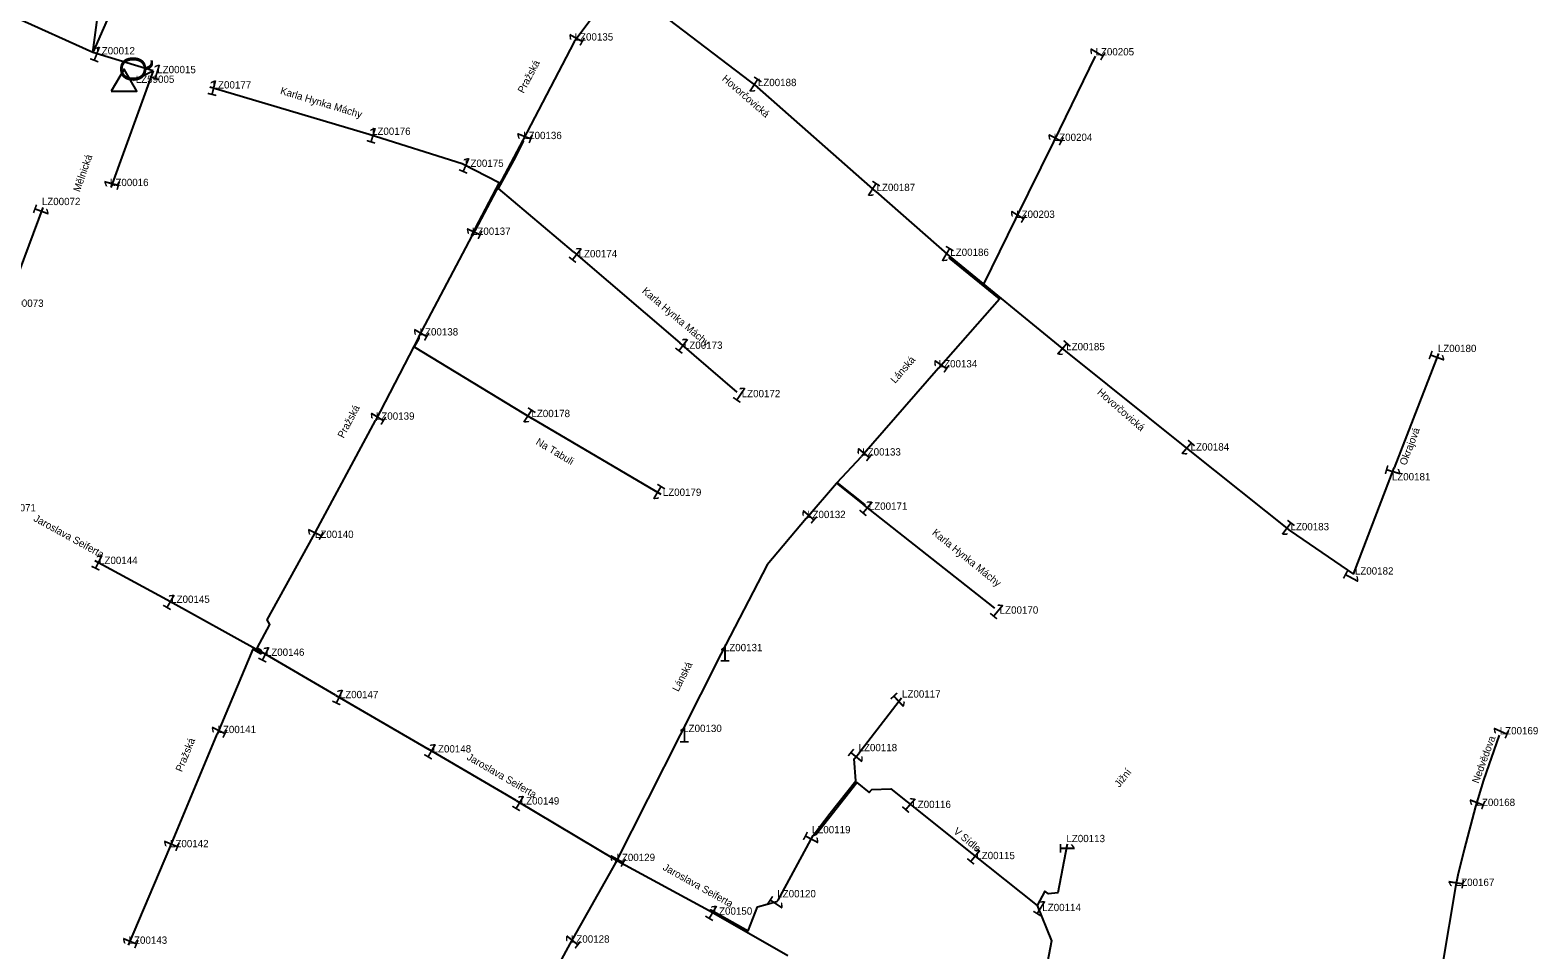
# Model space of a CAD drawing. Extents: x -736540 to -735418, y -1033000 to -1031598.
# Drawn here: x -736132 to -735616, y -1032655 to -1032341 of the extents above; entities that cross this region are included whole.
import ezdxf

# ---------------------------------------------------------------- set-up
doc = ezdxf.new("R2010")
doc.units = 0
for name, color, linetype in [('ftf_2010', 7, 'Continuous'), ('ftf_2050', 7, 'Continuous'), ('ftf_2080', 7, 'Continuous'), ('ftf_2210', 7, 'Continuous'), ('ftf_2240', 7, 'Continuous'), ('ftf_3010', 7, 'Continuous'), ('ftf_3010_ftf_3010_gtda_3015_gtda_3015_1', 7, 'Continuous'), ('ftf_3260', 7, 'Continuous'), ('ftf_3260_ftf_3260_gtda_3265_gtda_3265_1', 7, 'Continuous'), ('ftf_nu', 7, 'Continuous')]:
    doc.layers.add(name, color=color, linetype=linetype)

msp = doc.modelspace()

# ---------------------------------------------------------------- linework, layer by layer
at = {"layer": 'ftf_2010'}
for points in [[(-735916.06, -1032335.18), (-735883.11, -1032360.3)], [(-735945.72, -1032344.76), (-735963.27, -1032378.39)], [(-735767.69, -1032349.68), (-735781.89, -1032378.92)], [(-736070.38, -1032360.15), (-736015.89, -1032376.33)], [(-735842.62, -1032395.9), (-735883.11, -1032360.3)], [(-736015.89, -1032376.33), (-735984.08, -1032386.39)], [(-735963.27, -1032378.39), (-735980.62, -1032411)], [(-735946, -1032416.55), (-735971.61, -1032394.84), (-735966.42, -1032385.26), (-735963.14, -1032378.83), (-735963.27, -1032378.39)], [(-735781.89, -1032378.92), (-735794.83, -1032405.22)], [(-735984.08, -1032386.39), (-735971.41, -1032392.84), (-735980.89, -1032410.88), (-735980.62, -1032411)], [(-735842.62, -1032395.9), (-735817.38, -1032418.12)], [(-736127.45, -1032401.33), (-736140.32, -1032436.02)], [(-735794.83, -1032405.22), (-735805.8, -1032427.57)], [(-735998.88, -1032445.56), (-735980.62, -1032411)], [(-735946, -1032416.55), (-735909.66, -1032447.62)], [(-735821.15, -1032456.3), (-735800.35, -1032432.64), (-735817.39, -1032418.65), (-735817.38, -1032418.12)], [(-735817.38, -1032418.12), (-735777.75, -1032450.49)], [(-735998.88, -1032445.56), (-736013.7, -1032474.21)], [(-735998.88, -1032445.56), (-735998.88, -1032446.09), (-736000.43, -1032449.03), (-735960.4, -1032473.34)], [(-735890, -1032464.44), (-735909.66, -1032447.62)], [(-735777.75, -1032450.49), (-735735.23, -1032484.5)], [(-735650.28, -1032451.26), (-735665.39, -1032490.3)], [(-735821.15, -1032456.3), (-735847.57, -1032486.43)], [(-736034.95, -1032513.81), (-736013.7, -1032474.21)], [(-735916.05, -1032499.44), (-735960.4, -1032473.34)], [(-735846.61, -1032503.08), (-735846.43, -1032502.86), (-735855.81, -1032495.33), (-735847.57, -1032486.43)], [(-735735.23, -1032484.5), (-735700.99, -1032511.85)], [(-735679.34, -1032526.68), (-735665.39, -1032490.3)], [(-735866.45, -1032507.68), (-735856.02, -1032495.56), (-735846.61, -1032503.08)], [(-735801.94, -1032538.34), (-735846.61, -1032503.08)], [(-735866.45, -1032507.68), (-735879.73, -1032523.46), (-735895.6, -1032554)], [(-736052.56, -1032553.35), (-736052.75, -1032552.71), (-736054.14, -1032551.97), (-736049.81, -1032543.83), (-736050.76, -1032542.31), (-736034.95, -1032513.81)], [(-735700.99, -1032511.85), (-735679.34, -1032526.68)], [(-736109.63, -1032521.95), (-736085.03, -1032535.34)], [(-736085.03, -1032535.34), (-736052.56, -1032553.35)], [(-736052.56, -1032553.35), (-736052.88, -1032553.86), (-736055.65, -1032552.27), (-736067.87, -1032581.39)], [(-736027.35, -1032567.99), (-736052.56, -1032553.35)], [(-735895.6, -1032554), (-735909.49, -1032581.62)], [(-736027.35, -1032567.99), (-735995.75, -1032586.37)], [(-735833.85, -1032569.08), (-735848.46, -1032588)], [(-736084.05, -1032620.22), (-736067.87, -1032581.39)], [(-735909.49, -1032581.62), (-735931.68, -1032625.36)], [(-735629.52, -1032581.69), (-735634.87, -1032597.09), (-735637.61, -1032606.04)], [(-735965.62, -1032604.04), (-735995.75, -1032586.37)], [(-735864.01, -1032615.98), (-735858.25, -1032608.32), (-735849.42, -1032597.31), (-735850.04, -1032589.82), (-735848.46, -1032588)], [(-735864.01, -1032615.98), (-735863.04, -1032615.57), (-735849.11, -1032597.9), (-735844.85, -1032601.26), (-735844.01, -1032600.2), (-735837.47, -1032600), (-735831.94, -1032604.46)], [(-735965.62, -1032604.04), (-735931.43, -1032624.37), (-735931.68, -1032625.36)], [(-735831.94, -1032604.46), (-735809.79, -1032622.16)], [(-735637.61, -1032606.04), (-735641.44, -1032620.76), (-735643.6, -1032629.54), (-735644.46, -1032633.53)], [(-735876.03, -1032638.12), (-735864.01, -1032615.98)], [(-736098.09, -1032653.47), (-736084.05, -1032620.22)], [(-735809.79, -1032622.16), (-735787.44, -1032639.95)], [(-735777.21, -1032618.97), (-735780.45, -1032635.59), (-735783.63, -1032635.93), (-735784.8, -1032635.04), (-735787.44, -1032639.95)], [(-735931.68, -1032625.36), (-735947.19, -1032652.98)], [(-735931.68, -1032625.36), (-735930.94, -1032624.65), (-735899.61, -1032641.58)], [(-735644.46, -1032633.53), (-735648.88, -1032659.9)], [(-735899.61, -1032641.58), (-735899.03, -1032641.38), (-735886.29, -1032648.56), (-735883.11, -1032640.33), (-735876.51, -1032638.56), (-735876.03, -1032638.12)], [(-735899.61, -1032641.58), (-735872.69, -1032656.96)], [(-735787.44, -1032639.95), (-735782.6, -1032651.92), (-735784.87, -1032663.88)], [(-735947.19, -1032652.98), (-735961.39, -1032678.94)]]:
    msp.add_lwpolyline(points, dxfattribs=at)
at = {"layer": 'ftf_2050'}
for points in [[(-735916.25, -1032300.46), (-735916.9, -1032302.39), (-735937.34, -1032333.47), (-735945.72, -1032344.76)], [(-736110.31, -1032348.41), (-736105.13, -1032308.95)], [(-736093.72, -1032310.39), (-736110.31, -1032348.41)], [(-736110.31, -1032348.41), (-736137.15, -1032336.37)], [(-736089.68, -1032354.65), (-736110.31, -1032348.41)], [(-736089.68, -1032354.65), (-736104.23, -1032394.57)]]:
    msp.add_lwpolyline(points, dxfattribs=at)
at = {"layer": 'ftf_2080'}
msp.add_lwpolyline([(-736096.52, -1032357.84), (-736089.68, -1032354.65)], dxfattribs=at)
at = {"layer": 'ftf_2240'}
msp.add_lwpolyline([(-736104.02, -1032361.6), (-736095.31, -1032361.6), (-736099.66, -1032354.06)], close=True, dxfattribs=at)

# ---------------------------------------------------------------- texts
at = {"layer": 'ftf_2210'}
msp.add_text('-', height=2, rotation=142.5741, dxfattribs=at).set_placement((-735804.4, -1032427.39))
at = {"layer": 'ftf_3010'}
for rotation, p in [(60.9265, (-735943.76, -1032346.59)), (338.8471, (-736111.85, -1032350.6)), (59.232, (-735765.79, -1032351.57)), (342.7891, (-736091.06, -1032356.94)), (346.3947, (-736071.62, -1032362.53)), (146.7334, (-735881.14, -1032358.48)), (343.2002, (-736017.26, -1032378.63)), (68.7314, (-735961.08, -1032379.94)), (62.5434, (-735779.88, -1032380.69)), (336.7917, (-735985.7, -1032388.52)), (74.7806, (-736101.89, -1032395.88)), (147.3953, (-735840.67, -1032394.06)), (249.6995, (-736129.66, -1032399.82)), (58.6956, (-735792.94, -1032407.12)), (64.9934, (-735978.54, -1032412.69)), (321.7638, (-735948.12, -1032418.19)), (149.2459, (-735815.49, -1032416.21)), (60.094, (-735996.95, -1032447.41)), (322.7523, (-735911.75, -1032449.3)), (138.8674, (-735775.55, -1032448.96)), (250.0383, (-735652.5, -1032449.77)), (55.4482, (-735819.38, -1032458.31)), (325.9598, (-735892, -1032466.23)), (58.2826, (-736011.83, -1032476.13)), (146.7928, (-735958.43, -1032471.52)), (139.2546, (-735733.04, -1032482.95)), (50.853, (-735845.96, -1032488.57)), (253.6177, (-735667.7, -1032488.94)), (148.8032, (-735914.15, -1032497.55)), (320.1738, (-735848.77, -1032504.66)), (49.2186, (-735864.91, -1032509.87)), (143.0471, (-735698.9, -1032510.16)), (64.2232, (-736032.89, -1032515.52)), (333.817, (-736111.36, -1032524)), (241.7532, (-735681.33, -1032524.88)), (329.8797, (-736086.89, -1032537.26)), (320.1812, (-735804.1, -1032539.92)), (333.2302, (-736054.31, -1032555.38)), (334.9994, (-736029.03, -1032570.07)), (222.7228, (-735835.14, -1032566.73)), (63.8206, (-736065.82, -1032583.12)), (65.7162, (-735627.41, -1032583.35)), (329.6966, (-735997.62, -1032588.29)), (230.893, (-735850.07, -1032585.86)), (329.1944, (-735967.51, -1032605.94)), (318.4106, (-735834.15, -1032605.98)), (69.2099, (-735635.41, -1032607.57)), (242.4362, (-735866.01, -1032614.2)), (67.4382, (-736081.9, -1032621.82)), (320.5467, (-735811.94, -1032623.76)), (270, (-735779.81, -1032618.32)), (61.2005, (-735929.71, -1032627.18)), (81.0763, (-735642, -1032634.58)), (236.6337, (-735877.84, -1032636.15)), (329.3551, (-735901.5, -1032643.49)), (328.2545, (-735789.36, -1032641.82)), (67.4425, (-736095.94, -1032655.06)), (51.4719, (-735945.56, -1032655.1))]:
    msp.add_text('1', height=5.2, rotation=rotation, dxfattribs=at).set_placement(p)
for p in [(-735896.24, -1032556.6), (-735910.13, -1032584.22)]:
    msp.add_text('1', height=5.2, dxfattribs=at).set_placement(p)
at = {"layer": 'ftf_3010_ftf_3010_gtda_3015_gtda_3015_1'}
for s, p in [('LZ00135', (-735945.61, -1032344.32)), ('LZ00012', (-736109.14, -1032349.05)), ('LZ00205', (-735767.52, -1032349.4)), ('LZ00015', (-736088.31, -1032355.48)), ('LZ00177', (-736069.38, -1032360.71)), ('LZ00188', (-735882.96, -1032359.9)), ('LZ00176', (-736014.89, -1032376.56)), ('LZ00136', (-735963.2, -1032378)), ('LZ00204', (-735781.8, -1032378.63)), ('LZ00175', (-735983.08, -1032387.5)), ('LZ00187', (-735842.39, -1032395.75)), ('LZ00203', (-735794.65, -1032404.92)), ('LZ00137', (-735980.71, -1032410.72)), ('LZ00174', (-735944.26, -1032418.4)), ('LZ00186', (-735817.17, -1032417.92)), ('LZ00173', (-735908.24, -1032449.67)), ('LZ00185', (-735777.55, -1032450.17)), ('LZ00180', (-735650.49, -1032450.78)), ('LZ00134', (-735821.14, -1032456.01)), ('LZ00172', (-735888.48, -1032466.22)), ('LZ00139', (-736013.55, -1032473.89)), ('LZ00178', (-735960.38, -1032473.01)), ('LZ00184', (-735735.03, -1032484.43)), ('LZ00133', (-735847.27, -1032486.13)), ('LZ00181', (-735666.22, -1032494.63)), ('LZ00179', (-735915.47, -1032499.92)), ('LZ00171', (-735845.04, -1032504.67)), ('LZ00132', (-735866.14, -1032507.51)), ('LZ00140', (-736034.38, -1032514.3)), ('LZ00183', (-735700.86, -1032511.68)), ('LZ00144', (-736108.21, -1032523.19)), ('LZ00182', (-735678.85, -1032526.82)), ('LZ00145', (-736083.55, -1032536.48)), ('LZ00170', (-735800.28, -1032540.17)), ('LZ00146', (-736051.19, -1032554.58)), ('LZ00131', (-735894.6, -1032553)), ('LZ00147', (-736025.9, -1032569.05)), ('LZ00141', (-736067.72, -1032580.99)), ('LZ00130', (-735908.49, -1032580.62)), ('LZ00169', (-735629.32, -1032581.42)), ('LZ00148', (-735994.18, -1032587.61)), ('LZ00149', (-735964.06, -1032605.39)), ('LZ00116', (-735830.16, -1032606.59)), ('LZ00168', (-735637.26, -1032605.9)), ('LZ00142', (-736083.95, -1032619.99)), ('LZ00129', (-735931.3, -1032624.71)), ('LZ00115', (-735808.28, -1032624.06)), ('LZ00167', (-735644.36, -1032633.22)), ('LZ00150', (-735898.08, -1032643.03)), ('LZ00114', (-735785.71, -1032641.82)), ('LZ00143', (-736098.11, -1032652.98)), ('LZ00128', (-735946.87, -1032652.59))]:
    msp.add_text(s, height=2.5, dxfattribs=at).set_placement(p)
for s, p in [('LZ00016', (-736104.47, -1032394.06)), ('LZ00072', (-736127.77, -1032400.56)), ('LZ00073', (-736140.37, -1032435.32)), ('LZ00138', (-735998.62, -1032445.11)), ('LZ00071', (-736142.98, -1032505.21)), ('LZ00117', (-735833.67, -1032568.86)), ('LZ00118', (-735848.54, -1032587.18)), ('LZ00119', (-735864.48, -1032615.22)), ('LZ00113', (-735777.47, -1032618.25)), ('LZ00120', (-735876.32, -1032637.11))]:
    msp.add_text(s, height=2.5, rotation=0, dxfattribs=at).set_placement(p)
at = {"layer": 'ftf_3260'}
msp.add_text('Q', height=8.8, rotation=90, dxfattribs=at).set_placement((-736092.12, -1032358.62))
at = {"layer": 'ftf_3260_ftf_3260_gtda_3265_gtda_3265_1'}
msp.add_text('LZ59005', height=2.5, rotation=0, dxfattribs=at).set_placement((-736095.66, -1032358.78))
at = {"layer": 'ftf_nu'}
for s, rotation, p in [('Pražská', 62.2949, (-735963.03, -1032362.56)), ('Hovorčovická', 318.9274, (-735895.41, -1032357.68)), ('Karla Hynka Máchy', 343.2765, (-736046.44, -1032362.51)), ('Mělnická', 70.8064, (-736114.78, -1032396.24)), ('Karla Hynka Máchy', 319.7205, (-735922.78, -1032430.29)), ('Lánská', 49.0615, (-735836.01, -1032461.67)), ('Hovorčovická', 318.9274, (-735767.13, -1032464.83)), ('Pražská', 62.0338, (-736024.62, -1032480.4)), ('Okrajová', 68.9741, (-735661.36, -1032489.69)), ('Na Tabuli', 329.3057, (-735959.1, -1032482.14)), ('Jaroslava Seiferta', 331.1569, (-736130.81, -1032508.35)), ('Karla Hynka Máchy', 321.073, (-735823.6, -1032512.91)), ('Lánská', 62.9377, (-735910.16, -1032567.03)), ('Pražská', 67.7055, (-736079.86, -1032594.45)), ('Nedvědova', 69.8395, (-735636.56, -1032598.37)), ('Jaroslava Seiferta', 329.9326, (-735982.7, -1032589.87)), ('Jižní', 51.6208, (-735759.33, -1032599.73)), ('V Sídle', 320.5045, (-735816.28, -1032614.96)), ('Jaroslava Seiferta', 330.8182, (-735915.67, -1032627.56))]:
    msp.add_text(s, height=2.5, rotation=rotation, dxfattribs=at).set_placement(p)

doc.saveas('drawing.dxf')
